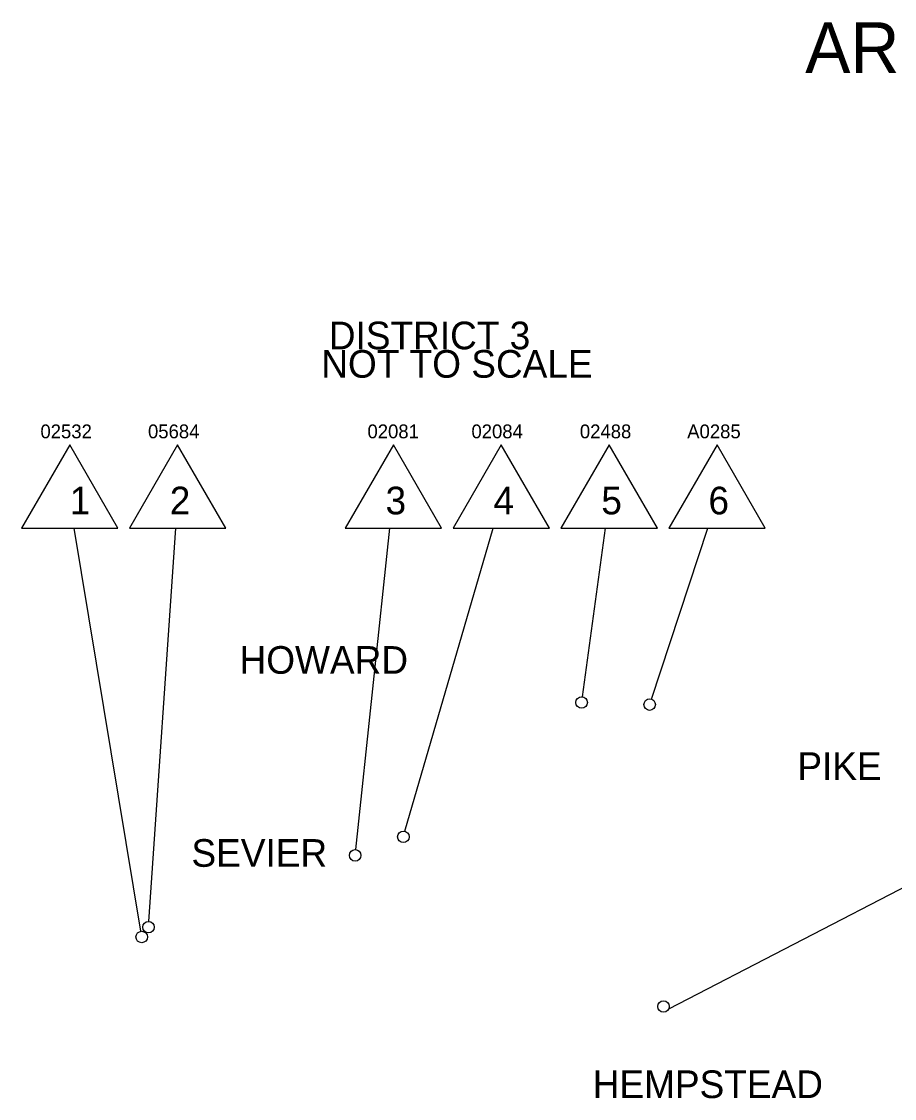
# Model space of a CAD drawing. Extents: x -43543 to 34500, y -13675 to 11152.
# Drawn here: x -10800 to -3227, y 1805 to 11152 of the extents above; entities that cross this region are included whole.
import ezdxf

# ---------------------------------------------------------------- set-up
doc = ezdxf.new("R2010")
doc.units = 0
for name, color, linetype in [('2', 7, 'Continuous'), ('R_Annotation', 7, 'Continuous'), ('R_No Plot', 7, 'Continuous')]:
    doc.layers.add(name, color=color, linetype=linetype)

msp = doc.modelspace()

# ---------------------------------------------------------------- linework, layer by layer
at = {"layer": 'R_Annotation'}
for p, q in [((-10381.7, 7477.2), (-10799.6, 6753.3)), ((-9963.7, 6753.3), (-10381.7, 7477.2)), ((-9445.8, 7477.2), (-9863.7, 6753.3)), ((-9027.8, 6753.3), (-9445.8, 7477.2)), ((-7574, 7477.2), (-7992, 6753.3)), ((-7156.1, 6753.3), (-7574, 7477.2)), ((-6638.1, 7477.2), (-7056.1, 6753.3)), ((-6220.2, 6753.3), (-6638.1, 7477.2)), ((-5702.3, 7477.2), (-6120.2, 6753.3)), ((-5284.3, 6753.3), (-5702.3, 7477.2)), ((-4766.4, 7477.2), (-5184.3, 6753.3)), ((-4348.4, 6753.3), (-4766.4, 7477.2)), ((-10799.6, 6753.3), (-9963.7, 6753.3)), ((-9765.6, 3255.9), (-10341.9, 6753.3)), ((-9863.7, 6753.3), (-9027.8, 6753.3)), ((-9695.3, 3341.7), (-9462.3, 6753.3)), ((-7992, 6753.3), (-7156.1, 6753.3)), ((-7899.6, 3964.4), (-7603.8, 6753.3)), ((-7473.3, 4124), (-6708.3, 6753.3)), ((-7056.1, 6753.3), (-6220.2, 6753.3)), ((-6120.2, 6753.3), (-5284.3, 6753.3)), ((-5934.4, 5290.7), (-5735.1, 6753.3)), ((-5335.4, 5271.1), (-4846, 6753.3)), ((-5184.3, 6753.3), (-4348.4, 6753.3)), ((-5184.8, 2583.3), (-2393.1, 4029.2))]:
    msp.add_line(p, q, dxfattribs=at)
for centre in [(-5941.2, 5241.1), (-5351, 5223.6), (-7487.3, 4076), (-7906, 3914.8), (-9698.7, 3291.8), (-9757.4, 3206.5), (-5230.6, 2603.4)]:
    msp.add_circle(centre, 50, dxfattribs=at)

# ---------------------------------------------------------------- texts
at = {"layer": '2'}
for s, height, p in [('ARKANSAS DEPARTMENT OF TRANSPORTATION', 440, (-4001.5, 10705.3)), ('NOT TO SCALE', 240, (-8199.7, 8060.5)), ('HOWARD', 240, (-8908.5, 5491)), ('PIKE', 240, (-4069.5, 4569.5)), ('SEVIER', 240, (-9325.8, 3815.6)), ('HEMPSTEAD', 240, (-5845, 1808.4))]:
    msp.add_text(s, height=height, dxfattribs=at).set_placement(p)
at = {"layer": 'R_Annotation'}
for s, p in [('DISTRICT 3', (-8134.1, 8307.2)), ('1', (-10381.7, 6874.6)), ('2', (-9513.8, 6874.6)), ('3', (-7642, 6874.6)), ('4', (-6706.2, 6874.6)), ('5', (-5770.3, 6874.6)), ('6', (-4841, 6874.6))]:
    msp.add_text(s, height=240, dxfattribs=at).set_placement(p)
at = {"layer": 'R_No Plot'}
for s, p in [('02532', (-10635.8, 7534.6)), ('05684', (-9702.8, 7534.6)), ('02081', (-7798.9, 7534.6)), ('02084', (-6897, 7534.6)), ('02488', (-5956.4, 7534.6)), ('A0285', (-5025.3, 7534.6))]:
    msp.add_text(s, height=120, dxfattribs=at).set_placement(p)

doc.saveas('drawing.dxf')
